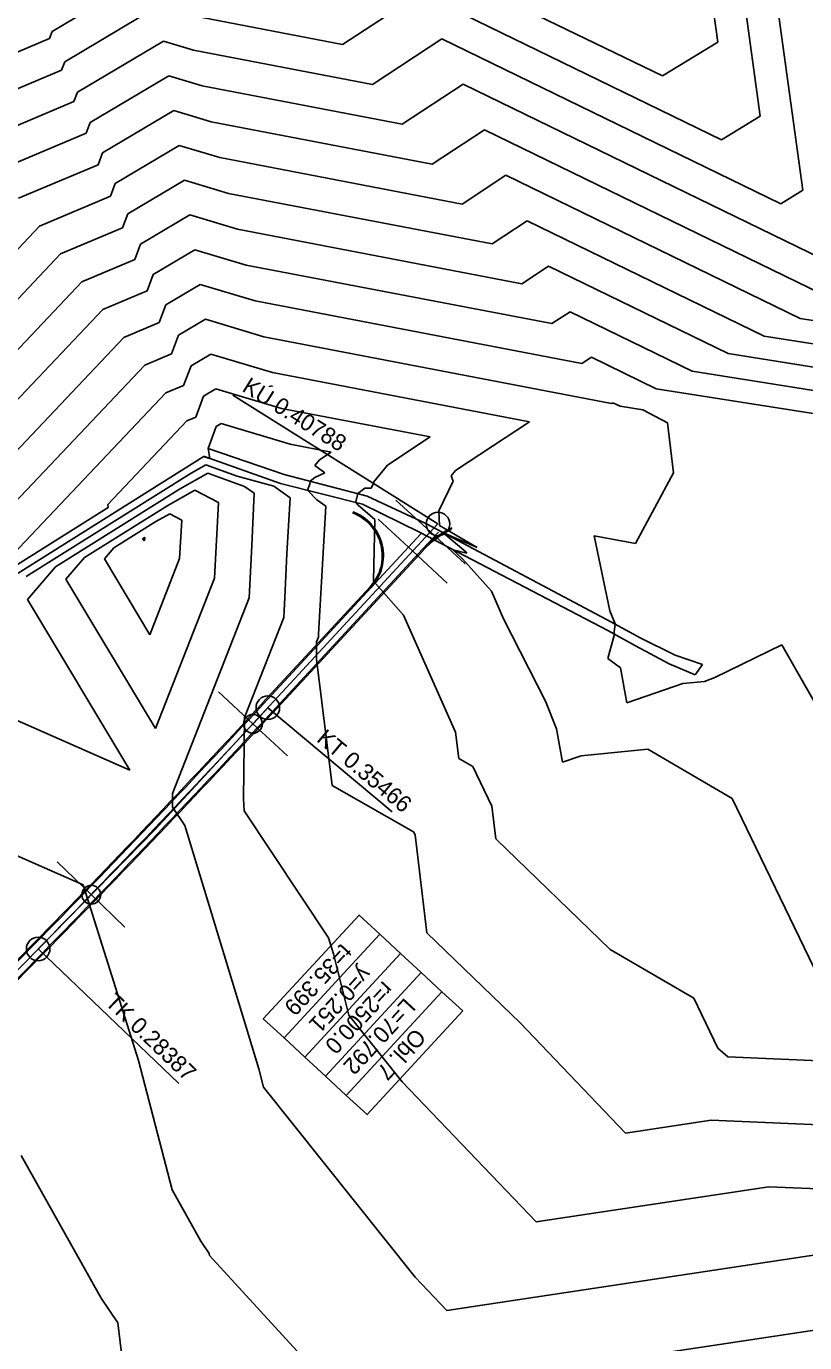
# Model space of a CAD drawing. Extents: x -549394 to -546608, y -1037055 to -1033629.
# Drawn here: x -548633.3 to -548467.8, y -1034201.2 to -1033921.5 of the extents above; entities that cross this region are included whole.
import ezdxf

# ---------------------------------------------------------------- set-up
doc = ezdxf.new("R2010")
doc.units = 0
for name, color, linetype in [('hlavni_vrst', 7, 'Continuous'), ('hrana_L', 7, 'Continuous'), ('norm_vrst', 7, 'Continuous'), ('POLYGONY_SITUACE_PO', 7, 'Continuous'), ('u_sirka_0_5m', 7, 'Continuous'), ('x_navrh_C122', 7, 'Continuous'), ('x_osa_C122', 7, 'Continuous'), ('x_popis_oblouky_C122', 7, 'Continuous'), ('x_popis_pricne_rezy_C122', 7, 'Continuous')]:
    doc.layers.add(name, color=color, linetype=linetype)

msp = doc.modelspace()

# ---------------------------------------------------------------- linework, layer by layer
at = {"layer": 'hlavni_vrst'}
for p, q in [((-548490.83, -1033892.03), (-548486.31, -1033924.79)), ((-548498.07, -1033932.01), (-548554.07, -1033904.76)), ((-548606.36, -1033909.81), (-548627.8, -1033922.53)), ((-548628.37, -1033924.06), (-548652.86, -1033934.37)), ((-548627.8, -1033922.53), (-548628.37, -1033924.06)), ((-548486.31, -1033924.79), (-548498.07, -1033932.01)), ((-548600.78, -1033946.76), (-548614.38, -1033954.83)), ((-548592.15, -1033949.35), (-548600.78, -1033946.76)), ((-548540.66, -1033959.22), (-548592.15, -1033949.35)), ((-548614.38, -1033954.83), (-548615.41, -1033957.58)), ((-548531.35, -1033953.11), (-548540.66, -1033959.22)), ((-548468.8, -1033983.55), (-548531.35, -1033953.11)), ((-548615.41, -1033957.58), (-548630.48, -1033963.92)), ((-548630.48, -1033963.92), (-548664.24, -1033999.57)), ((-548595.2, -1033983.71), (-548600.96, -1033987.12)), ((-548582.81, -1033987.44), (-548595.2, -1033983.71)), ((-548451.08, -1033986.35), (-548468.8, -1033983.55)), ((-548600.96, -1033987.12), (-548602.44, -1033991.09)), ((-548508.87, -1034001.61), (-548582.81, -1033987.44)), ((-548602.44, -1033991.09), (-548608.09, -1033993.47)), ((-548608.09, -1033993.47), (-548657.97, -1034046.13)), ((-548508.63, -1034001.45), (-548508.87, -1034001.61)), ((-548507.05, -1034002.22), (-548508.63, -1034001.45)), ((-548502.27, -1034002.98), (-548507.05, -1034002.22)), ((-548497.03, -1034005.7), (-548502.27, -1034002.98)), ((-548495.74, -1034016.38), (-548497.03, -1034005.7)), ((-548594.72, -1034016.44), (-548600.73, -1034019.84)), ((-548586.9, -1034019.27), (-548594.72, -1034016.44)), ((-548503.8, -1034031.37), (-548495.74, -1034016.38)), ((-548584.85, -1034020.69), (-548586.9, -1034019.27)), ((-548600.73, -1034019.84), (-548627.1, -1034036.36)), ((-548585.34, -1034031.77), (-548584.85, -1034020.69)), ((-548512.55, -1034029.73), (-548503.8, -1034031.37)), ((-548509.28, -1034045.68), (-548512.55, -1034029.73)), ((-548585.94, -1034042.9), (-548585.34, -1034031.77)), ((-548627.1, -1034036.36), (-548633.02, -1034043.25)), ((-548633.02, -1034043.25), (-548611.26, -1034079.53)), ((-548602.21, -1034084.51), (-548585.94, -1034042.9)), ((-548508.11, -1034048.48), (-548509.28, -1034045.68)), ((-548508.31, -1034050.2), (-548508.11, -1034048.48)), ((-548508.27, -1034050.67), (-548508.31, -1034050.2)), ((-548509.68, -1034055.82), (-548508.27, -1034050.67)), ((-548472.7, -1034052.91), (-548486.92, -1034059.84)), ((-548457.04, -1034080.4), (-548472.7, -1034052.91)), ((-548506.98, -1034057.77), (-548509.68, -1034055.82)), ((-548505.66, -1034065.25), (-548506.98, -1034057.77)), ((-548493.75, -1034061.14), (-548505.66, -1034065.25)), ((-548489.16, -1034060.7), (-548493.75, -1034061.14)), ((-548486.92, -1034059.84), (-548489.16, -1034060.7)), ((-548611.26, -1034079.53), (-548638.98, -1034067.36)), ((-548602.24, -1034087.01), (-548602.21, -1034084.51)), ((-548602.22, -1034087.38), (-548602.24, -1034087.01)), ((-548599.61, -1034091.31), (-548602.22, -1034087.38)), ((-548583.87, -1034143.01), (-548599.61, -1034091.31)), ((-548582.87, -1034146.92), (-548583.87, -1034143.01)), ((-548550.64, -1034187.34), (-548582.87, -1034146.92)), ((-548463.15, -1034182.22), (-548543.89, -1034194.39)), ((-548543.89, -1034194.39), (-548550.64, -1034187.34))]:
    msp.add_line(p, q, dxfattribs=at)
at = {"layer": 'hrana_L'}
for p, q in [((-548594.66, -1034011.2), (-548578.47, -1034016.69)), ((-548579.25, -1034018.6), (-548595.61, -1034012.8)), ((-548578.47, -1034016.69), (-548560.81, -1034021.29)), ((-548561.83, -1034023.04), (-548579.25, -1034018.6)), ((-548548.37, -1034027.11), (-548560.81, -1034021.29)), ((-548549.74, -1034028.97), (-548561.83, -1034023.04)), ((-548508.87, -1034048.06), (-548548.37, -1034027.11)), ((-548549.74, -1034028.97), (-548509.65, -1034049.9)), ((-548503.81, -1034053.16), (-548509.65, -1034049.9)), ((-548508.87, -1034048.06), (-548502.78, -1034051.42)), ((-548496.63, -1034056.94), (-548503.81, -1034053.16)), ((-548502.78, -1034051.42), (-548495.34, -1034055.08)), ((-548495.34, -1034055.08), (-548489.59, -1034057.06)), ((-548491.15, -1034059.3), (-548496.63, -1034056.94)), ((-548489.59, -1034057.06), (-548491.15, -1034059.3))]:
    msp.add_line(p, q, dxfattribs=at)
at = {"layer": 'norm_vrst'}
for p, q in [((-548482.37, -1033903.58), (-548477.27, -1033940.53)), ((-548549.53, -1033914.43), (-548566.09, -1033925.31)), ((-548485.51, -1033945.59), (-548549.53, -1033914.43)), ((-548473.9, -1033915.12), (-548468.22, -1033956.26)), ((-548605.25, -1033917.2), (-548625.12, -1033928.99)), ((-548566.09, -1033925.31), (-548599.62, -1033918.89)), ((-548604.13, -1033924.59), (-548622.43, -1033935.45)), ((-548597.75, -1033926.5), (-548604.13, -1033924.59)), ((-548544.98, -1033924.1), (-548559.73, -1033933.79)), ((-548472.94, -1033959.16), (-548544.98, -1033924.1)), ((-548559.73, -1033933.79), (-548597.75, -1033926.5)), ((-548625.12, -1033928.99), (-548625.78, -1033930.77)), ((-548625.78, -1033930.77), (-548648.39, -1033940.28)), ((-548603.01, -1033931.98), (-548619.75, -1033941.91)), ((-548595.89, -1033934.12), (-548603.01, -1033931.98)), ((-548622.43, -1033935.45), (-548623.19, -1033937.47)), ((-548553.37, -1033942.27), (-548595.89, -1033934.12)), ((-548540.44, -1033933.77), (-548553.37, -1033942.27)), ((-548460.37, -1033972.73), (-548540.44, -1033933.77)), ((-548623.19, -1033937.47), (-548643.91, -1033946.19)), ((-548601.9, -1033939.37), (-548617.07, -1033948.37)), ((-548594.02, -1033941.74), (-548601.9, -1033939.37)), ((-548477.27, -1033940.53), (-548485.51, -1033945.59)), ((-548620.59, -1033944.17), (-548639.43, -1033952.1)), ((-548619.75, -1033941.91), (-548620.59, -1033944.17)), ((-548547.01, -1033950.75), (-548594.02, -1033941.74)), ((-548535.9, -1033943.44), (-548547.01, -1033950.75)), ((-548461.15, -1033979.82), (-548535.9, -1033943.44)), ((-548617.07, -1033948.37), (-548618, -1033950.87)), ((-548618, -1033950.87), (-548634.96, -1033958.01)), ((-548599.67, -1033954.15), (-548611.7, -1033961.29)), ((-548590.28, -1033956.97), (-548599.67, -1033954.15)), ((-548534.3, -1033967.7), (-548590.28, -1033956.97)), ((-548468.22, -1033956.26), (-548472.94, -1033959.16)), ((-548611.7, -1033961.29), (-548612.81, -1033964.28)), ((-548598.55, -1033961.54), (-548609.01, -1033967.75)), ((-548588.41, -1033964.59), (-548598.55, -1033961.54)), ((-548526.81, -1033962.78), (-548534.3, -1033967.7)), ((-548476.45, -1033987.28), (-548526.81, -1033962.78)), ((-548612.81, -1033964.28), (-548626, -1033969.83)), ((-548527.94, -1033976.18), (-548588.41, -1033964.59)), ((-548609.01, -1033967.75), (-548610.22, -1033970.98)), ((-548597.44, -1033968.93), (-548606.33, -1033974.21)), ((-548586.54, -1033972.2), (-548597.44, -1033968.93)), ((-548626, -1033969.83), (-548662.99, -1034008.88)), ((-548610.22, -1033970.98), (-548621.52, -1033975.74)), ((-548606.33, -1033974.21), (-548607.63, -1033977.69)), ((-548521.58, -1033984.65), (-548586.54, -1033972.2)), ((-548522.26, -1033972.45), (-548527.94, -1033976.18)), ((-548484.1, -1033991.02), (-548522.26, -1033972.45)), ((-548621.52, -1033975.74), (-548661.73, -1034018.19)), ((-548607.63, -1033977.69), (-548617.05, -1033981.65)), ((-548596.32, -1033976.32), (-548603.65, -1033980.67)), ((-548584.67, -1033979.82), (-548596.32, -1033976.32)), ((-548515.22, -1033993.13), (-548584.67, -1033979.82)), ((-548617.05, -1033981.65), (-548660.48, -1034027.51)), ((-548603.65, -1033980.67), (-548605.03, -1033984.39)), ((-548517.72, -1033982.11), (-548521.58, -1033984.65)), ((-548491.75, -1033994.75), (-548517.72, -1033982.11)), ((-548605.03, -1033984.39), (-548612.57, -1033987.56)), ((-548612.57, -1033987.56), (-548659.22, -1034036.82)), ((-548448.05, -1033991.78), (-548476.45, -1033987.28)), ((-548594.09, -1033991.1), (-548598.28, -1033993.58)), ((-548580.94, -1033995.05), (-548594.09, -1033991.1)), ((-548445.03, -1033997.2), (-548484.1, -1033991.02)), ((-548598.28, -1033993.58), (-548599.85, -1033997.79)), ((-548513.17, -1033991.78), (-548515.22, -1033993.13)), ((-548499.4, -1033998.49), (-548513.17, -1033991.78)), ((-548526.36, -1034005.51), (-548580.94, -1033995.05)), ((-548442, -1034002.63), (-548491.75, -1033994.75)), ((-548603.61, -1033999.38), (-548637.27, -1034034.91)), ((-548599.85, -1033997.79), (-548603.61, -1033999.38)), ((-548595.59, -1034000.04), (-548597.25, -1034004.5)), ((-548592.97, -1033998.49), (-548595.59, -1034000.04)), ((-548579.07, -1034002.67), (-548592.97, -1033998.49)), ((-548457.93, -1034005.05), (-548499.4, -1033998.49)), ((-548547.43, -1034008.73), (-548579.07, -1034002.67)), ((-548599.14, -1034005.29), (-548615.96, -1034023.06)), ((-548597.25, -1034004.5), (-548599.14, -1034005.29)), ((-548542.04, -1034015.88), (-548526.36, -1034005.51)), ((-548592.91, -1034006.5), (-548594.66, -1034011.2)), ((-548591.86, -1034005.88), (-548592.91, -1034006.5)), ((-548577.2, -1034010.29), (-548591.86, -1034005.88)), ((-548594.66, -1034011.2), (-548594.27, -1034013.28)), ((-548594.66, -1034011.2), (-548594.66, -1034011.2)), ((-548594.66, -1034011.2), (-548594.66, -1034011.2)), ((-548594.66, -1034011.2), (-548594.66, -1034011.2)), ((-548594.66, -1034011.2), (-548594.66, -1034011.2)), ((-548594.66, -1034011.2), (-548594.66, -1034011.2)), ((-548568.49, -1034011.96), (-548577.2, -1034010.29)), ((-548556.52, -1034014.75), (-548547.43, -1034008.73)), ((-548595.73, -1034012.97), (-548639.5, -1034040.41)), ((-548595.59, -1034012.89), (-548595.73, -1034012.97)), ((-548595.27, -1034013), (-548595.59, -1034012.89)), ((-548594.27, -1034013.28), (-548595.27, -1034013)), ((-548571.97, -1034014.8), (-548570.99, -1034013.61)), ((-548570.99, -1034013.61), (-548568.49, -1034011.96)), ((-548598.23, -1034016.4), (-548633.3, -1034038.39)), ((-548595.15, -1034014.66), (-548598.23, -1034016.4)), ((-548588.48, -1034017.08), (-548595.15, -1034014.66)), ((-548569.82, -1034016.37), (-548571.97, -1034014.8)), ((-548571.95, -1034017.38), (-548569.82, -1034016.37)), ((-548559.44, -1034018.28), (-548556.52, -1034014.75)), ((-548542.95, -1034016.98), (-548542.04, -1034015.88)), ((-548580.67, -1034019.2), (-548588.48, -1034017.08)), ((-548577.22, -1034021.65), (-548580.67, -1034019.2)), ((-548573.51, -1034020.06), (-548573.05, -1034018.76)), ((-548573.05, -1034018.76), (-548572.92, -1034018.14)), ((-548572.92, -1034018.14), (-548571.95, -1034017.38)), ((-548562.83, -1034020.76), (-548561.36, -1034019.63)), ((-548561.36, -1034019.63), (-548559.97, -1034019.61)), ((-548559.97, -1034019.61), (-548559.4, -1034018.42)), ((-548559.4, -1034018.42), (-548559.44, -1034018.28)), ((-548545.58, -1034024.4), (-548542.59, -1034018.14)), ((-548542.59, -1034018.14), (-548542.95, -1034016.98)), ((-548597.46, -1034020.01), (-548603.23, -1034023.27)), ((-548592.46, -1034022.69), (-548597.46, -1034020.01)), ((-548577.91, -1034033.56), (-548577.22, -1034021.65)), ((-548571.51, -1034022.06), (-548573.51, -1034020.06)), ((-548569.59, -1034023.43), (-548571.51, -1034022.06)), ((-548563.26, -1034022.67), (-548563.21, -1034022.51)), ((-548563.21, -1034022.51), (-548562.83, -1034020.76)), ((-548615.89, -1034023.73), (-548645.71, -1034042.43)), ((-548603.23, -1034023.27), (-548620.89, -1034034.34)), ((-548615.96, -1034023.06), (-548615.89, -1034023.73)), ((-548602.8, -1034025.05), (-548605.73, -1034026.7)), ((-548600.26, -1034026.41), (-548602.8, -1034025.05)), ((-548593.32, -1034038.72), (-548592.46, -1034022.69)), ((-548571.15, -1034050.62), (-548569.59, -1034023.43)), ((-548562.74, -1034023.2), (-548563.26, -1034022.67)), ((-548559.23, -1034026.26), (-548562.74, -1034023.2)), ((-548545.48, -1034027.58), (-548545.58, -1034024.4)), ((-548605.73, -1034026.7), (-548614.69, -1034032.32)), ((-548600.7, -1034034.54), (-548600.26, -1034026.41)), ((-548559.5, -1034039.39), (-548559.23, -1034026.26)), ((-548537.43, -1034032.21), (-548545.48, -1034027.58)), ((-548608.49, -1034030.3), (-548608.54, -1034030.37)), ((-548608.54, -1034030.37), (-548608.26, -1034030.84)), ((-548608.23, -1034030.14), (-548608.49, -1034030.3)), ((-548608.26, -1034030.84), (-548608.08, -1034030.37)), ((-548608.14, -1034030.09), (-548608.23, -1034030.14)), ((-548608.07, -1034030.13), (-548608.14, -1034030.09)), ((-548608.08, -1034030.37), (-548608.07, -1034030.13)), ((-548539.86, -1034033.14), (-548544.78, -1034029.01)), ((-548544.78, -1034029.01), (-548537.43, -1034032.21)), ((-548614.69, -1034032.32), (-548616.7, -1034034.66)), ((-548578.25, -1034041.38), (-548577.91, -1034033.56)), ((-548540.57, -1034034.6), (-548542.6, -1034032.7)), ((-548542.6, -1034032.7), (-548539.68, -1034033.46)), ((-548539.68, -1034033.46), (-548539.86, -1034033.14)), ((-548537.43, -1034032.21), (-548537.43, -1034032.21)), ((-548537.43, -1034032.21), (-548537.43, -1034032.21)), ((-548537.43, -1034032.21), (-548537.43, -1034032.21)), ((-548537.43, -1034032.21), (-548537.43, -1034032.21)), ((-548620.89, -1034034.34), (-548624.86, -1034038.95)), ((-548616.7, -1034034.66), (-548607.04, -1034050.77)), ((-548607.04, -1034050.77), (-548600.7, -1034034.54)), ((-548534.44, -1034041.51), (-548540.57, -1034034.6)), ((-548624.86, -1034038.95), (-548605.82, -1034070.71)), ((-548605.82, -1034070.71), (-548593.32, -1034038.72)), ((-548578.56, -1034047.08), (-548578.25, -1034041.38)), ((-548553.09, -1034046.62), (-548559.5, -1034039.39)), ((-548531.83, -1034047.39), (-548534.44, -1034041.51)), ((-548586.89, -1034068.39), (-548578.56, -1034047.08)), ((-548542.06, -1034071.44), (-548553.09, -1034046.62)), ((-548522.9, -1034064.85), (-548531.83, -1034047.39)), ((-548571.63, -1034055.96), (-548571.58, -1034052.28)), ((-548571.58, -1034052.28), (-548571.18, -1034051.26)), ((-548571.18, -1034051.26), (-548571.16, -1034050.99)), ((-548571.16, -1034050.99), (-548571.15, -1034050.62)), ((-548568.28, -1034082.84), (-548571.63, -1034055.96)), ((-548520.59, -1034070.75), (-548522.9, -1034064.85)), ((-548587.15, -1034085.62), (-548586.89, -1034068.39)), ((-548541.35, -1034077.07), (-548542.06, -1034071.44)), ((-548519.35, -1034077.84), (-548520.59, -1034070.75)), ((-548501.19, -1034075.12), (-548515.38, -1034076.47)), ((-548483.22, -1034085.6), (-548501.19, -1034075.12)), ((-548538.35, -1034078.78), (-548541.35, -1034077.07)), ((-548515.38, -1034076.47), (-548519.35, -1034077.84)), ((-548534.35, -1034087.19), (-548538.35, -1034078.78)), ((-548550.96, -1034092.68), (-548568.28, -1034082.84)), ((-548586.99, -1034088.17), (-548587.15, -1034085.62)), ((-548465.87, -1034121.49), (-548483.22, -1034085.6)), ((-548569.05, -1034115.21), (-548586.99, -1034088.17)), ((-548533.51, -1034094.13), (-548534.35, -1034087.19)), ((-548550.66, -1034093.3), (-548550.96, -1034092.68)), ((-548548.15, -1034114.12), (-548550.66, -1034093.3)), ((-548509.17, -1034117.64), (-548533.51, -1034094.13)), ((-548621.22, -1034103.91), (-548639, -1034096.11)), ((-548609.42, -1034141.28), (-548621.22, -1034103.91)), ((-548528.34, -1034133.25), (-548548.15, -1034114.12)), ((-548568.02, -1034118.59), (-548569.05, -1034115.21)), ((-548491.42, -1034127.98), (-548509.17, -1034117.64)), ((-548564.7, -1034131.6), (-548568.02, -1034118.59)), ((-548486.29, -1034138.6), (-548491.42, -1034127.98)), ((-548553.4, -1034145.77), (-548564.7, -1034131.6)), ((-548505.89, -1034156.71), (-548528.34, -1034133.25)), ((-548484.16, -1034140.51), (-548486.29, -1034138.6)), ((-548602.28, -1034168.75), (-548609.42, -1034141.28)), ((-548422.38, -1034143.07), (-548484.16, -1034140.51)), ((-548524.89, -1034175.55), (-548553.4, -1034145.77)), ((-548487.74, -1034153.97), (-548505.89, -1034156.71)), ((-548424.65, -1034156.59), (-548487.74, -1034153.97)), ((-548617.38, -1034191.77), (-548634.4, -1034161.46)), ((-548596.19, -1034179.64), (-548602.28, -1034168.75)), ((-548475.45, -1034168.1), (-548524.89, -1034175.55)), ((-548426.93, -1034170.11), (-548475.45, -1034168.1)), ((-548594.41, -1034182.27), (-548596.19, -1034179.64)), ((-548594.36, -1034182.69), (-548594.41, -1034182.27)), ((-548573.46, -1034205.49), (-548594.36, -1034182.69)), ((-548613.85, -1034197), (-548617.38, -1034191.77)), ((-548612.48, -1034207.99), (-548613.85, -1034197)), ((-548450.86, -1034196.34), (-548510.41, -1034205.32))]:
    msp.add_line(p, q, dxfattribs=at)
at = {"layer": 'POLYGONY_SITUACE_PO'}
for centre in [(-548545.79, -1034027.23), (-548581.95, -1034066.28), (-548630.77, -1034117.54)]:
    msp.add_circle(centre, 2.5, dxfattribs=at)
at = {"layer": 'u_sirka_0_5m'}
for centre in [(-548585.11, -1034069.7), (-548619.48, -1034106.02)]:
    msp.add_circle(centre, 2, dxfattribs=at)
at = {"layer": 'x_navrh_C122'}
for p, q in [((-548582.86, -1034065.43), (-548549.42, -1034029.31)), ((-548549.05, -1034032.59), (-548545.65, -1034028.99)), ((-548543.16, -1034028.49), (-548542.9, -1034028.4)), ((-548581.03, -1034067.13), (-548549.05, -1034032.59)), ((-548663.48, -1034149.14), (-548631.66, -1034116.66)), ((-548661.7, -1034150.89), (-548629.88, -1034118.41))]:
    msp.add_line(p, q, dxfattribs=at)
for points in [[(-548580.85, -1034067.3), (-548548.86, -1034032.76)], [(-548583.05, -1034065.26), (-548560.23, -1034040.61)], [(-548663.66, -1034148.96), (-548631.84, -1034116.49)], [(-548654.51, -1034143.91), (-548629.7, -1034118.59)]]:
    msp.add_lwpolyline(points, dxfattribs=at)
for centre, radius, start, end in [((-548567.38, -1034033.99), 9.75, 317.205, 69.4791), ((-548567.38, -1034033.99), 10, 317.205, 69.4791), ((-548534.37, -1034046.17), 20, 114.7866, 137.205), ((-548534.37, -1034046.17), 19.75, 116.422, 137.205), ((-550416.42, -1032367.84), 2498.5, 315.58253, 317.20498), ((-550416.42, -1032367.84), 2498.75, 315.58253, 317.20498), ((-550416.42, -1032367.84), 2501.25, 315.58253, 317.20498), ((-550416.42, -1032367.84), 2501.5, 315.58253, 317.20498)]:
    msp.add_arc(centre, radius, start, end, dxfattribs=at)
at = {"layer": 'x_osa_C122'}
msp.add_lwpolyline([(-548717.69, -1034296.78), (-548699.62, -1034250.33), (-548699.62, -1034250.33), (-548677.63, -1034183.22), (-548677.63, -1034183.22), (-548677.63, -1034183.22), (-548664.6, -1034152.07), (-548606, -1034092.26), (-548545.79, -1034027.23)], dxfattribs=at)
msp.add_arc((-550416.42, -1032367.84), 2500, 315.58253, 317.20498, dxfattribs=at)
at = {"layer": 'x_popis_oblouky_C122'}
for points in [[(-548589.4, -1033999.87), (-548545.79, -1034027.23)], [(-548581.95, -1034066.28), (-548555.49, -1034088.42)], [(-548630.77, -1034117.54), (-548600.88, -1034146.14)]]:
    msp.add_lwpolyline(points, dxfattribs=at)
for points in [[(-548558.16, -1034114.42), (-548578.5, -1034136.47), (-548582.91, -1034132.4), (-548562.57, -1034110.35)], [(-548553.75, -1034118.49), (-548574.09, -1034140.54), (-548578.5, -1034136.47), (-548558.16, -1034114.42)], [(-548549.34, -1034122.56), (-548569.69, -1034144.61), (-548574.09, -1034140.54), (-548553.75, -1034118.49)], [(-548544.93, -1034126.63), (-548565.28, -1034148.68), (-548569.69, -1034144.61), (-548549.34, -1034122.56)], [(-548540.52, -1034130.7), (-548560.87, -1034152.75), (-548565.28, -1034148.68), (-548544.93, -1034126.63)]]:
    msp.add_lwpolyline(points, close=True, dxfattribs=at)
at = {"layer": 'x_popis_pricne_rezy_C122'}
for points in [[(-548554.71, -1034022.14), (-548547.37, -1034028.93), (-548540.03, -1034035.73)], [(-548558.48, -1034026.22), (-548551.14, -1034033.01), (-548543.81, -1034039.8)], [(-548592.44, -1034062.89), (-548585.12, -1034069.7), (-548577.79, -1034076.5)], [(-548626.7, -1034099.03), (-548619.52, -1034105.98), (-548612.33, -1034112.93)]]:
    msp.add_lwpolyline(points, dxfattribs=at)

# ---------------------------------------------------------------- texts
at = {"layer": 'x_popis_oblouky_C122'}
for s, rotation, p in [('KÚ 0.40788', 327.9017, (-548587.64, -1033998.85)), ('KT 0.35466', 320.069, (-548571.79, -1034073.27)), ('t=35.399', 227.3171, (-548566.28, -1034116.16)), ('y=0.251', 227.3171, (-548562.09, -1034120.98)), ('r=2500.0', 227.3171, (-548557.45, -1034124.15)), ('TK 0.28387', 316.2602, (-548616.74, -1034129.17)), ('L=70.792', 227.3171, (-548552.85, -1034127.76)), ('Obl. 7', 227.3171, (-548550.62, -1034134.19))]:
    msp.add_text(s, height=3.5, rotation=rotation, dxfattribs=at).set_placement(p)

doc.saveas('drawing.dxf')
